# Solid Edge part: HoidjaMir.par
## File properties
Author: Türk
Template: Iso Part.par
Last saved by: Türk
Revision: 28
Application: Solid Edge
Accuracy: 0,990
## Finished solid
Body 1: solid body, 35 faces, 77 edges, 42 vertices.
  Faces by surface: plane 20, cylinder 13, torus 2
  Edges by curve: line 51, circle 26
Bounding box of the edges (mm; curved faces can reach further): 221.000 x 108.000 x 188.000, from (-181, -58, -89) to (40, 50, 99).
Cylindrical faces by radius (mm): R4 x1, R5 x1, R10 x1, R10.5 x4, R18 x1, R25 x2, R32.5 x1, R40 x2
Toroidal faces (ring radius, tube radius in mm): R10.5 r2.5 x2
Planar faces by outward normal: +x 2, +y 2, +z 3, -x 3, -y 2, -z 4, oblique 4
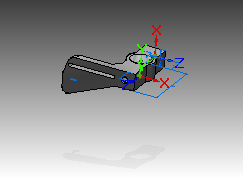
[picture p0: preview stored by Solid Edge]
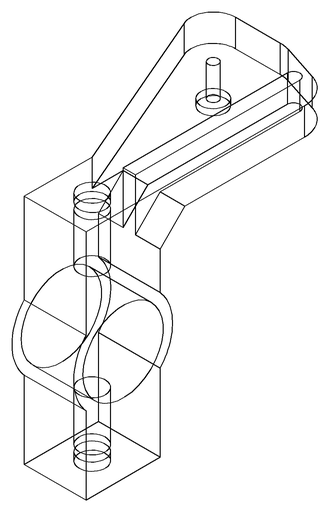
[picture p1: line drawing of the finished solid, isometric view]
